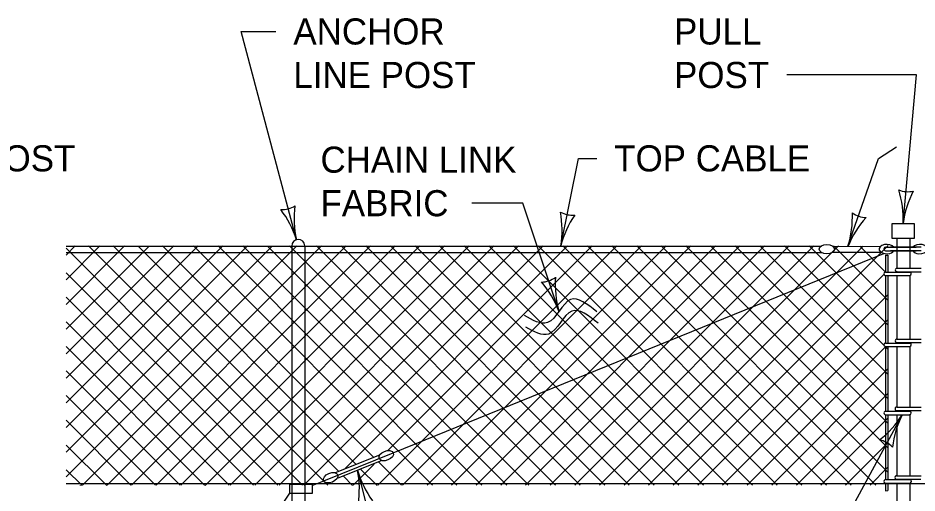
# Model space of a CAD drawing. Extents: x 49973.1 to 50021, y 49987.6 to 50015.4.
# Drawn here: x 49976.495 to 49978.561, y 50009.018 to 50010.109 of the extents above; entities that cross this region are included whole.
import ezdxf

# ---------------------------------------------------------------- set-up
doc = ezdxf.new("R2010")
doc.units = 0
for name, color, linetype in [('Level 1', 7, 'Continuous'), ('Level 2', 7, 'Continuous'), ('Level 3', 7, 'Continuous'), ('Level 6', 7, 'Continuous')]:
    doc.layers.add(name, color=color, linetype=linetype)

msp = doc.modelspace()

# ---------------------------------------------------------------- linework, layer by layer
at = {"layer": 'Level 1'}
for p, q in [((49978.5141, 50009.603), (49978.5141, 50009.5348)), ((49978.5441, 50009.603), (49978.5441, 50009.5346)), ((49976.6055, 50009.5645), (49976.6266, 50009.5856)), ((49976.6055, 50009.3381), (49976.853, 50009.5856)), ((49976.6055, 50009.2817), (49976.9094, 50009.5856)), ((49976.6055, 50009.2251), (49976.966, 50009.5856)), ((49976.6055, 50009.5079), (49976.6832, 50009.5856)), ((49976.6055, 50009.4513), (49976.7398, 50009.5856)), ((49976.6055, 50009.1685), (49977.0226, 50009.5856)), ((49976.6055, 50009.0553), (49977.1358, 50009.5856)), ((49976.6055, 50009.3947), (49976.7963, 50009.5855)), ((49976.6055, 50009.1119), (49977.0791, 50009.5855)), ((49976.6055, 50009.5855), (49978.341, 50009.5855)), ((49976.6055, 50009.5808), (49977.149, 50009.0363)), ((49976.6055, 50009.5706), (49978.3414, 50009.5706)), ((49976.6431, 50009.0363), (49977.1924, 50009.5856)), ((49976.6571, 50009.5856), (49977.2067, 50009.0363)), ((49976.6997, 50009.0363), (49977.249, 50009.5856)), ((49976.7136, 50009.5856), (49977.2321, 50009.0676)), ((49976.7561, 50009.0363), (49977.3054, 50009.5856)), ((49976.7709, 50009.585), (49977.2721, 50009.0835)), ((49976.8127, 50009.0363), (49977.362, 50009.5856)), ((49976.827, 50009.5856), (49977.3127, 50009.0997)), ((49976.8693, 50009.0363), (49977.4186, 50009.5856)), ((49976.8983, 50009.5856), (49977.4471, 50009.0363)), ((49976.9259, 50009.0363), (49977.4752, 50009.5856)), ((49976.955, 50009.5856), (49977.5036, 50009.0363)), ((49976.9825, 50009.0363), (49977.5318, 50009.5856)), ((49977.0116, 50009.5856), (49977.5609, 50009.0363)), ((49977.0391, 50009.0363), (49977.5884, 50009.5856)), ((49977.0681, 50009.5855), (49977.618, 50009.0363)), ((49977.0955, 50009.0363), (49977.6448, 50009.5856)), ((49977.1187, 50009.5856), (49977.669, 50009.0363)), ((49977.124, 50009.5855), (49977.124, 50008.5907)), ((49977.1521, 50009.0363), (49977.7014, 50009.5856)), ((49977.154, 50009.5855), (49977.154, 50008.5907)), ((49977.181, 50009.5856), (49977.73, 50009.0363)), ((49977.2376, 50009.5856), (49977.7869, 50009.0363)), ((49977.2452, 50009.0728), (49977.758, 50009.5856)), ((49977.2944, 50009.5856), (49977.8437, 50009.0363)), ((49977.3219, 50009.0363), (49977.8712, 50009.5856)), ((49977.3447, 50009.1157), (49977.8146, 50009.5856)), ((49977.351, 50009.5856), (49977.8997, 50009.0363)), ((49977.3574, 50009.1102), (49978.4843, 50009.5686)), ((49977.3785, 50009.0363), (49977.9278, 50009.5856)), ((49977.4075, 50009.5856), (49977.9568, 50009.0363)), ((49977.4349, 50009.0363), (49977.9842, 50009.5856)), ((49977.4639, 50009.5856), (49978.0132, 50009.0363)), ((49977.4915, 50009.0363), (49978.0408, 50009.5856)), ((49977.5205, 50009.5856), (49978.0698, 50009.0363)), ((49977.5481, 50009.0363), (49978.0974, 50009.5856)), ((49977.5771, 50009.5856), (49978.1264, 50009.0363)), ((49977.6047, 50009.0363), (49978.154, 50009.5856)), ((49977.6337, 50009.5856), (49978.183, 50009.0363)), ((49977.6613, 50009.0363), (49978.2106, 50009.5856)), ((49977.6902, 50009.5856), (49978.2395, 50009.0363)), ((49977.718, 50009.0363), (49978.2672, 50009.5856)), ((49977.7467, 50009.5856), (49978.296, 50009.0363)), ((49977.7745, 50009.0363), (49978.3238, 50009.5856)), ((49977.8035, 50009.5856), (49978.3528, 50009.0363)), ((49977.831, 50009.0363), (49978.3802, 50009.5856)), ((49977.8599, 50009.5856), (49978.4092, 50009.0363)), ((49977.8875, 50009.0363), (49978.4367, 50009.5855)), ((49977.9166, 50009.5856), (49978.4659, 50009.0363)), ((49977.9441, 50009.0363), (49978.4941, 50009.5863)), ((49977.9732, 50009.5856), (49978.4935, 50009.0659)), ((49978.0298, 50009.5856), (49978.4935, 50009.1218)), ((49978.0864, 50009.5856), (49978.4935, 50009.1782)), ((49978.143, 50009.5856), (49978.4935, 50009.235)), ((49978.1994, 50009.5856), (49978.4935, 50009.2914)), ((49978.256, 50009.5856), (49978.4935, 50009.3482)), ((49978.3126, 50009.5856), (49978.4935, 50009.4044)), ((49978.3673, 50009.5849), (49978.4769, 50009.5847)), ((49978.3675, 50009.5715), (49978.4779, 50009.5715)), ((49978.3692, 50009.5856), (49978.4935, 50009.4612)), ((49978.4296, 50009.5855), (49978.4882, 50009.5252)), ((49978.4885, 50009.5825), (49978.5591, 50009.5825)), ((49978.4885, 50009.5744), (49978.5589, 50009.5744)), ((49978.5701, 50009.5825), (49978.4995, 50009.5825)), ((49978.5701, 50009.5744), (49978.4997, 50009.5744)), ((49978.4885, 50009.5648), (49978.4885, 50009.5255)), ((49978.4885, 50009.5648), (49978.4935, 50009.5648)), ((49978.4935, 50009.5648), (49978.4935, 50009.5255)), ((49978.5144, 50009.5346), (49978.5706, 50009.5346)), ((49978.5144, 50009.5265), (49978.5704, 50009.5265)), ((49976.6055, 50009.5242), (49977.0921, 50009.0363)), ((49978.0005, 50009.0363), (49978.4846, 50009.5204)), ((49978.4885, 50009.5174), (49978.4885, 50009.3631)), ((49978.4886, 50009.5255), (49978.5448, 50009.5255)), ((49978.4886, 50009.5174), (49978.5446, 50009.5174)), ((49978.4935, 50009.5174), (49978.4935, 50009.3631)), ((49978.5141, 50009.5172), (49978.5141, 50009.372)), ((49978.5441, 50009.5174), (49978.5441, 50009.3721)), ((49976.6055, 50009.4677), (49977.0365, 50009.0363)), ((49978.0571, 50009.0363), (49978.4939, 50009.4731)), ((49976.6055, 50009.4111), (49976.9803, 50009.0363)), ((49978.1137, 50009.0363), (49978.4941, 50009.4167)), ((49978.4886, 50009.3627), (49978.5448, 50009.3627)), ((49978.5144, 50009.3718), (49978.5706, 50009.3718)), ((49978.5144, 50009.3637), (49978.5704, 50009.3637)), ((49976.6055, 50009.3549), (49976.924, 50009.0363)), ((49978.1703, 50009.0363), (49978.4888, 50009.3548)), ((49978.4885, 50009.3545), (49978.4885, 50009.2065)), ((49978.4886, 50009.3546), (49978.5446, 50009.3546)), ((49978.4935, 50009.3548), (49978.4935, 50009.2065)), ((49978.5141, 50009.355), (49978.5141, 50009.2155)), ((49978.5441, 50009.3551), (49978.5441, 50009.2154)), ((49978.2269, 50009.0363), (49978.4938, 50009.3032)), ((49976.6055, 50009.2984), (49976.8674, 50009.0363)), ((49976.6055, 50009.242), (49976.8111, 50009.0363)), ((49978.2835, 50009.0363), (49978.494, 50009.2468)), ((49978.4884, 50009.2061), (49978.5446, 50009.2061)), ((49978.4884, 50009.198), (49978.5444, 50009.198)), ((49978.4885, 50009.1982), (49978.4885, 50009.0488)), ((49978.4935, 50009.1979), (49978.4935, 50009.0488)), ((49978.5141, 50009.198), (49978.5141, 50009.0578)), ((49978.5142, 50009.2154), (49978.5704, 50009.2154)), ((49978.5142, 50009.2073), (49978.5702, 50009.2073)), ((49978.5441, 50009.1982), (49978.5441, 50009.0577)), ((49976.6055, 50009.1854), (49976.7546, 50009.0363)), ((49978.3401, 50009.0363), (49978.4939, 50009.1901)), ((49976.6055, 50009.1279), (49976.699, 50009.0356)), ((49978.3965, 50009.0363), (49978.4937, 50009.1335)), ((49977.1975, 50009.046), (49977.3574, 50009.1102)), ((49977.3259, 50009.105), (49977.2241, 50009.0644)), ((49977.3307, 50009.0926), (49977.2283, 50009.0518)), ((49977.2653, 50009.0363), (49977.3134, 50009.0844)), ((49977.2823, 50009.0728), (49977.3205, 50009.0356)), ((49977.3238, 50009.089), (49977.3764, 50009.0361)), ((49978.4531, 50009.0363), (49978.494, 50009.0772)), ((49976.6055, 50009.0716), (49976.6424, 50009.0356)), ((49977.2428, 50009.0566), (49977.2639, 50009.0356)), ((49978.5138, 50009.0578), (49978.57, 50009.0578)), ((49976.6055, 50009.0401), (49978.4511, 50009.0401)), ((49976.638, 50009.0361), (49976.6379, 50009.0356)), ((49976.638, 50009.0361), (49976.6381, 50009.0356)), ((49976.638, 50009.0361), (49976.6381, 50009.0356)), ((49976.9254, 50009.0358), (49976.9256, 50009.0356)), ((49976.9254, 50009.0358), (49976.9254, 50009.0356)), ((49976.9254, 50009.0358), (49976.9255, 50009.0356)), ((49976.9254, 50009.0358), (49976.9254, 50009.0356)), ((49977.171, 50009.0354), (49977.1975, 50009.046)), ((49978.4511, 50009.04), (49980.3238, 50009.04)), ((49978.4885, 50009.0407), (49978.4885, 50009.0233)), ((49978.4887, 50009.0488), (49978.5449, 50009.0488)), ((49978.4887, 50009.0407), (49978.5447, 50009.0407)), ((49978.4935, 50009.0407), (49978.4935, 50009.0241)), ((49978.5138, 50009.0497), (49978.5698, 50009.0497)), ((49978.5141, 50009.0407), (49978.5141, 50008.5907)), ((49978.5441, 50009.0407), (49978.5441, 50008.5907)), ((49978.4885, 50009.0233), (49978.4935, 50009.0241))]:
    msp.add_line(p, q, dxfattribs=at)
for points in [[(49978.5542, 50009.6373), (49978.5542, 50009.603), (49978.5033, 50009.603), (49978.5033, 50009.6373)], [(49977.1188, 50009.0378), (49977.1188, 50009.0181), (49977.1715, 50009.0181), (49977.1715, 50009.0378)]]:
    msp.add_lwpolyline(points, close=True, dxfattribs=at)
for centre, radius, start, end in [((49977.139, 50009.5855), 0.015, 2.6745, 180.7625), ((49978.4884, 50009.5784), 0.00405, 89.5405, 270.6652), ((49978.5145, 50009.5306), 0.00405, 87.9212, 274.9002), ((49978.4887, 50009.5215), 0.00405, 87.9212, 274.9002), ((49978.5435, 50009.5216), 0.00417, 282.5816, 72.0167), ((49978.4887, 50009.3587), 0.00405, 87.9212, 274.9002), ((49978.5145, 50009.3678), 0.00405, 87.9212, 274.9002), ((49978.5435, 50009.3588), 0.00417, 282.5816, 72.0167), ((49978.4885, 50009.2021), 0.00405, 87.9212, 274.9002), ((49978.5143, 50009.2114), 0.00405, 87.9212, 274.9002), ((49978.5433, 50009.2022), 0.00417, 282.5816, 72.0167), ((49978.5139, 50009.0538), 0.00405, 87.9212, 274.9002), ((49978.4885, 50009.0448), 0.00405, 87.9212, 274.9002), ((49978.5436, 50009.0449), 0.00417, 282.5816, 72.0167)]:
    msp.add_arc(centre, radius, start, end, dxfattribs=at)
for centre, major_axis in [((49978.3537, 50009.5782), (-0.0175, 0.0001)), ((49977.3411, 50009.1039), (0.0162, 0.0066)), ((49977.2134, 50009.0533), (0.0162, 0.0066))]:
    msp.add_ellipse(centre, major_axis=major_axis, ratio=0.610393, dxfattribs=at)
for centre, major_axis, start_param, end_param in [((49978.4911, 50009.5784), (-0.0175, 0.0001), 3.539885, 7.997344), ((49978.5675, 50009.5784), (0.0175, 0.0001), 4.569027, 9.026485), ((49978.4911, 50009.5784), (-0.0175, 0.0001), 1.714159, 2.761839), ((49978.5675, 50009.5784), (0.0175, 0.0001), 3.521347, 4.569027)]:
    msp.add_ellipse(centre, major_axis=major_axis, ratio=0.610393, start_param=start_param, end_param=end_param, dxfattribs=at)
at = {"layer": 'Level 3'}
for p, q in [((49977.1348, 50009.5999), (49977.0082, 50010.0783)), ((49977.0082, 50010.0783), (49977.0878, 50010.0783)), ((49978.5597, 50009.9783), (49978.2617, 50009.9783)), ((49978.5288, 50009.6373), (49978.5597, 50009.9783)), ((49978.4724, 50009.7861), (49978.5134, 50009.8133)), ((49977.7424, 50009.5855), (49977.7832, 50009.7868)), ((49977.7832, 50009.7868), (49977.825, 50009.7868)), ((49978.4021, 50009.5848), (49978.4724, 50009.7861)), ((49977.6551, 50009.6838), (49977.5375, 50009.6838)), ((49977.738, 50009.436), (49977.6551, 50009.6838)), ((49978.5268, 50009.198), (49978.26, 50008.706)), ((49977.2754, 50009.0706), (49977.3357, 50008.8312)), ((49977.1188, 50009.0181), (49976.8863, 50008.6638))]:
    msp.add_line(p, q, dxfattribs=at)
for centre, radius, start, end in [((49978.5402, 50009.765), 0.0548, 247.0497, 282.772), ((49978.296, 50009.6465), 0.233, 357.7382, 16.988), ((49978.7492, 50009.6085), 0.2223, 152.3669, 172.5504), ((49977.102, 50009.7239), 0.0548, 266.9596, 302.682), ((49977.3518, 50009.6479), 0.2223, 172.2768, 192.4603), ((49976.9127, 50009.5293), 0.233, 17.6481, 36.898), ((49977.7684, 50009.7111), 0.0548, 240.4135, 276.1359), ((49977.5122, 50009.6216), 0.233, 351.102, 10.3519), ((49977.958, 50009.5314), 0.2223, 145.7307, 165.9142), ((49978.1793, 50009.6529), 0.233, 342.9989, 2.2487), ((49978.608, 50009.5009), 0.2223, 137.6276, 157.8111), ((49978.4456, 50009.7054), 0.0548, 232.3104, 268.0327), ((49977.6973, 50009.5576), 0.0548, 270.6438, 306.3662), ((49977.9516, 50009.4979), 0.2223, 175.961, 196.1445), ((49977.521, 50009.3513), 0.233, 21.3323, 40.5822), ((49978.3378, 50009.3151), 0.2223, 308.0447, 328.2282), ((49978.7352, 50009.0938), 0.233, 153.416, 172.6659), ((49978.4638, 50009.0863), 0.0548, 42.7275, 78.4499), ((49977.0571, 50009.0285), 0.2223, 350.7315, 10.915), ((49977.4993, 50009.1352), 0.233, 196.1028, 215.3526)]:
    msp.add_arc(centre, radius, start, end, dxfattribs=at)
at = {"layer": 'Level 6'}
for points in [[(49977.8249, 50009.4346), (49977.7647, 50009.4625), (49977.7117, 50009.4097), (49977.6588, 50009.4258)], [(49977.8278, 50009.4082), (49977.7676, 50009.4361), (49977.7146, 50009.3833), (49977.6617, 50009.3994)]]:
    msp.add_spline(points, degree=3, dxfattribs=at)

# ---------------------------------------------------------------- texts
at = {"layer": 'Level 2'}
for s, p in [('ANCHOR', (49977.1278, 50010.0483)), ('PULL ', (49978.0025, 50010.0483)), ('LINE POST', (49977.1278, 50009.9483)), ('POST', (49978.0025, 50009.9483)), ('LINE POST', (49976.2078, 50009.7569)), ('TOP CABLE', (49977.865, 50009.7568)), ('CHAIN LINK', (49977.1901, 50009.7538)), ('FABRIC', (49977.1901, 50009.6538))]:
    msp.add_text(s, height=0.06, dxfattribs=at).set_placement(p)

doc.saveas('drawing.dxf')
